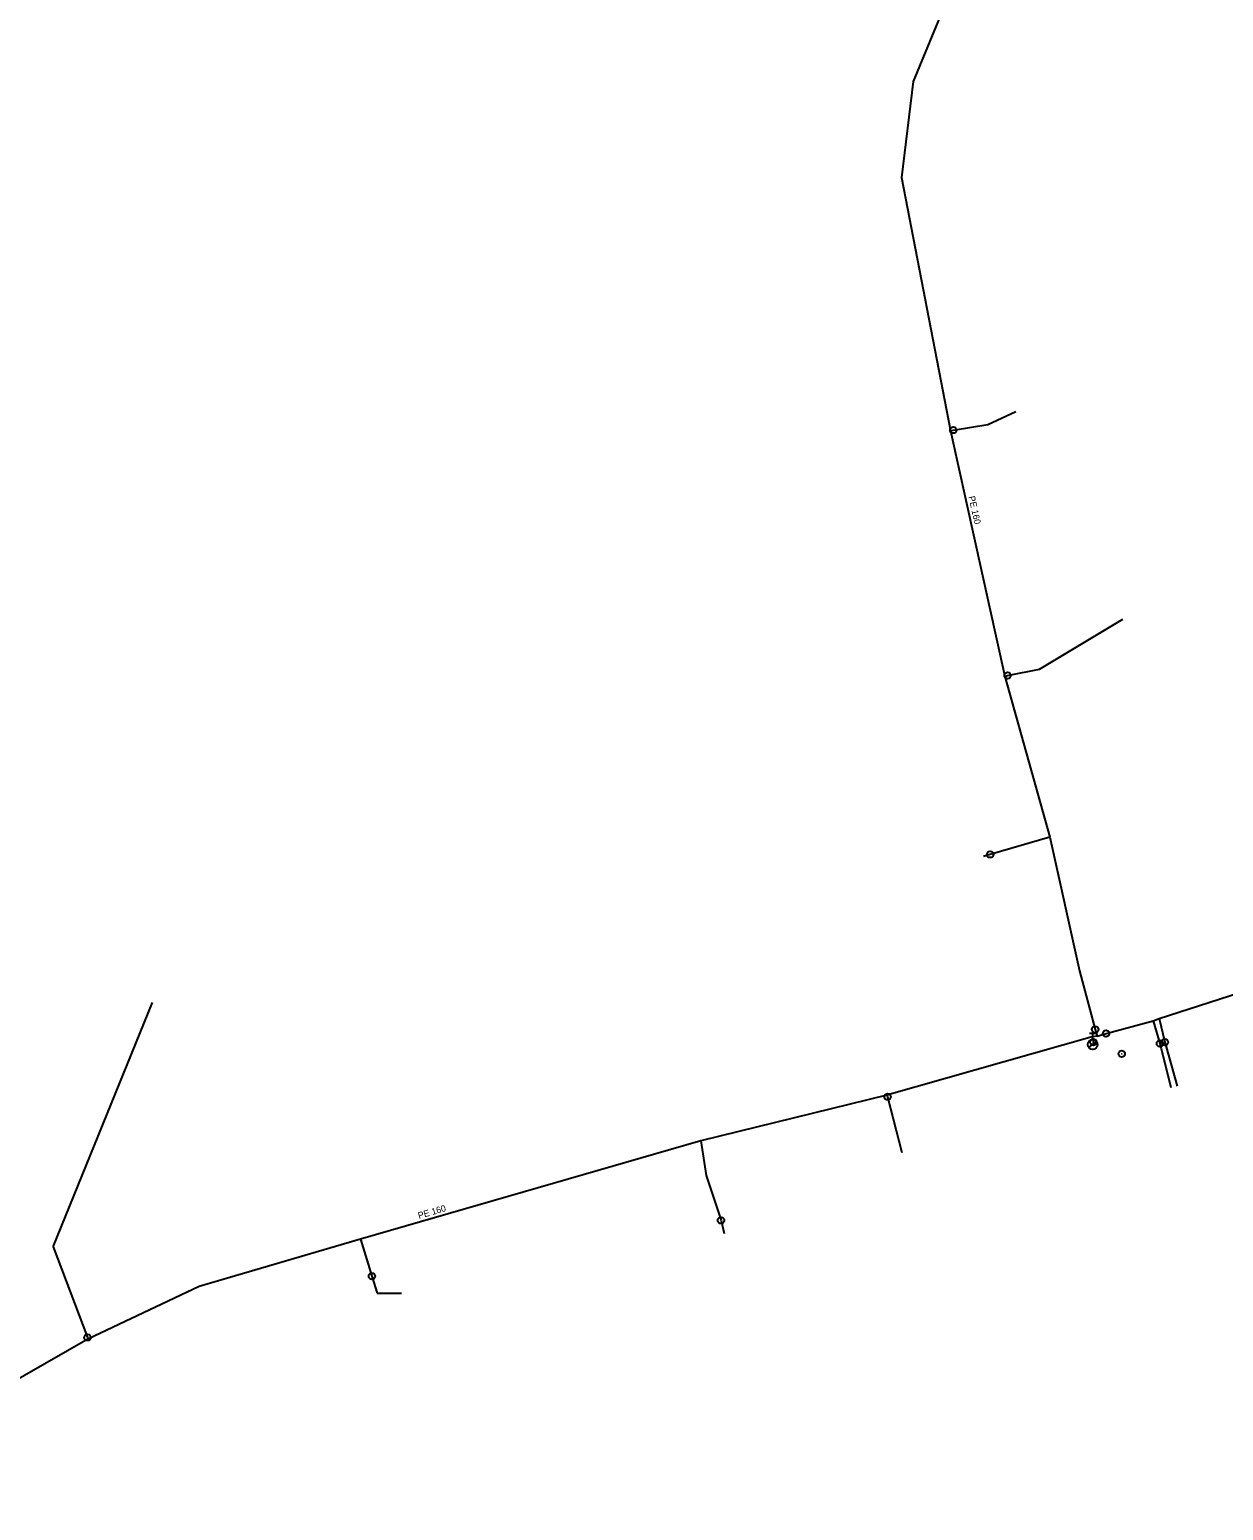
# Model space of a CAD drawing. Extents: x -681947 to -681511, y -1163527 to -1163073.
# Drawn here: x -681859 to -681767.6, y -1163486.4 to -1163373 of the extents above; entities that cross this region are included whole.
import ezdxf

# ---------------------------------------------------------------- set-up
doc = ezdxf.new("R2010")
doc.units = 0
for name, color, linetype in [('Hydranty', 7, 'Continuous'), ('Označník', 7, 'Continuous'), ('Popis vodovodních řadů', 7, 'Continuous'), ('Vod přípojky-voda pitná', 7, 'Continuous'), ('Vodovodní řad', 7, 'Continuous'), ('Vodovodní šoupata', 7, 'Continuous')]:
    doc.layers.add(name, color=color, linetype=linetype)

msp = doc.modelspace()

# ---------------------------------------------------------------- linework, layer by layer
at = {"layer": 'Hydranty'}
for p, q in [((-681777.89, -1163450.91), (-681777.3, -1163450.45)), ((-681777.85, -1163449.81), (-681777.35, -1163449.81)), ((-681777.6, -1163450.31), (-681777.6, -1163449.81))]:
    msp.add_line(p, q, dxfattribs=at)
msp.add_circle((-681777.6, -1163450.68), 0.375, dxfattribs=at)
at = {"layer": 'Označník'}
for radius in [0.25, 0.0005]:
    msp.add_circle((-681775.38, -1163451.4), radius, dxfattribs=at)
at = {"layer": 'Vod přípojky-voda pitná'}
for points in [[(-681785.64, -1163403.2), (-681783.48, -1163402.19)], [(-681788.49, -1163403.69), (-681788.28, -1163403.62), (-681785.64, -1163403.2)], [(-681781.69, -1163421.93), (-681775.3, -1163418.1)], [(-681784.34, -1163422.49), (-681784.12, -1163422.42), (-681781.69, -1163421.93)], [(-681780.88, -1163434.81), (-681785.45, -1163436.12), (-681785.97, -1163436.29)], [(-681857.23, -1163466.18), (-681849.62, -1163447.46)], [(-681772.96, -1163448.87), (-681772.45, -1163450.61), (-681772.35, -1163450.98)], [(-681772.51, -1163448.69), (-681772.08, -1163450.5), (-681771.97, -1163450.85)], [(-681772.35, -1163450.98), (-681771.63, -1163453.97)], [(-681771.97, -1163450.85), (-681771.14, -1163453.86)], [(-681793.38, -1163454.57), (-681793.31, -1163454.68), (-681792.21, -1163458.95)], [(-681807.62, -1163458.07), (-681807.21, -1163460.71), (-681806.07, -1163464.15), (-681805.83, -1163465.16)], [(-681857.23, -1163466.18), (-681854.59, -1163473.11), (-681854.55, -1163473.25)], [(-681833.67, -1163465.59), (-681832.8, -1163468.43), (-681832.41, -1163469.73)], [(-681832.41, -1163469.73), (-681830.53, -1163469.72)]]:
    msp.add_lwpolyline(points, dxfattribs=at)
at = {"layer": 'Vodovodní řad'}
for points in [[(-681787.71, -1163368.07), (-681791.36, -1163376.92), (-681792.25, -1163384.29), (-681788.49, -1163403.69), (-681784.34, -1163422.49), (-681780.88, -1163434.81), (-681778.61, -1163445.05), (-681777.42, -1163449.54)], [(-681776.58, -1163449.84), (-681772.96, -1163448.87), (-681772.51, -1163448.69), (-681743.28, -1163439.28), (-681739.93, -1163438.87), (-681724.33, -1163438.15), (-681708.67, -1163441.09)], [(-681777.42, -1163449.54), (-681777.27, -1163450.03)], [(-681777.64, -1163450.09), (-681793.38, -1163454.57), (-681807.62, -1163458.07), (-681833.67, -1163465.59), (-681846.03, -1163469.22), (-681854.55, -1163473.25), (-681877.46, -1163486.36)], [(-681777.27, -1163450.03), (-681777.64, -1163450.09)], [(-681777.64, -1163450.09), (-681777.55, -1163450.5)], [(-681777.55, -1163450.5), (-681777.6, -1163450.68)], [(-681777.27, -1163450.03), (-681776.58, -1163449.84)]]:
    msp.add_lwpolyline(points, dxfattribs=at)
at = {"layer": 'Vodovodní šoupata'}
for centre in [(-681788.28, -1163403.62), (-681784.12, -1163422.42), (-681785.45, -1163436.12), (-681777.42, -1163449.54), (-681776.58, -1163449.84), (-681777.55, -1163450.5), (-681772.45, -1163450.61), (-681772.08, -1163450.5), (-681793.31, -1163454.68), (-681806.07, -1163464.15), (-681832.8, -1163468.43), (-681854.59, -1163473.11)]:
    msp.add_circle(centre, 0.25, dxfattribs=at)

# ---------------------------------------------------------------- texts
at = {"layer": 'Popis vodovodních řadů'}
for rotation, p in [(282.4481, (-681787.12, -1163408.73)), (16.1021, (-681829.2, -1163464.04))]:
    msp.add_text('PE 160', height=0.5, rotation=rotation, dxfattribs=at).set_placement(p)

doc.saveas('drawing.dxf')
